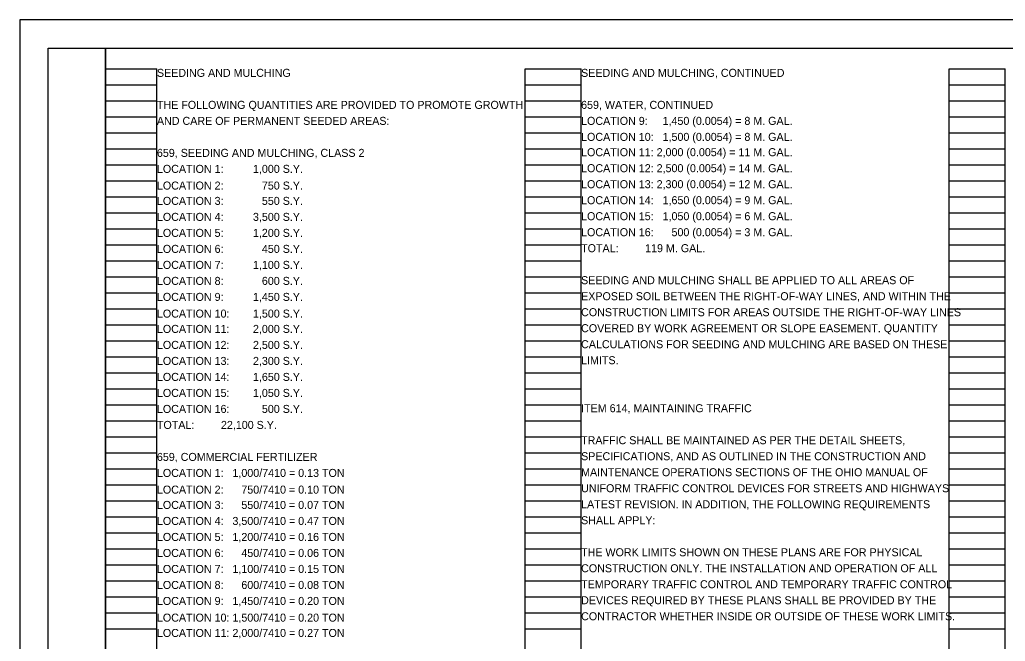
# Model space of a CAD drawing. Extents: x 0 to 34, y 0 to 22.
# Drawn here: x 0 to 17.24, y 11.12 to 22 of the extents above; entities that cross this region are included whole.
import ezdxf

# ---------------------------------------------------------------- set-up
doc = ezdxf.new("R2010")
doc.units = 0
for name, color, linetype in [('SH_Border', 7, 'Continuous'), ('SH_Cut_Line', 7, 'Continuous'), ('SH_Data', 7, 'Continuous'), ('SH_Text', 7, 'Continuous')]:
    doc.layers.add(name, color=color, linetype=linetype)

msp = doc.modelspace()

# ---------------------------------------------------------------- linework, layer by layer
at = {"layer": 'SH_Border'}
for points in [[(0.5, 21.5), (1.5, 21.5), (1.5, 0.5), (0.5, 0.5)], [(1.5, 21.5), (33.5, 21.5), (33.5, 0.5), (1.5, 0.5)]]:
    msp.add_lwpolyline(points, close=True, dxfattribs=at)
at = {"layer": 'SH_Cut_Line'}
msp.add_lwpolyline([(0, 0), (34, 0), (34, 22), (0, 22)], close=True, dxfattribs=at)
at = {"layer": 'SH_Data'}
for p, q in [((1.5, 0.98), (1.5, 21.14)), ((1.5, 21.14), (2.4, 21.14)), ((2.4, 0.98), (2.4, 21.14)), ((8.84, 0.98), (8.84, 21.14)), ((8.84, 21.14), (9.82, 21.14)), ((9.82, 0.98), (9.82, 21.14)), ((16.26, 0.98), (16.26, 21.14)), ((16.26, 21.14), (17.24, 21.14)), ((17.24, 0.98), (17.24, 21.14)), ((1.5, 20.86), (2.4, 20.86)), ((8.84, 20.86), (9.82, 20.86)), ((16.26, 20.86), (17.24, 20.86)), ((1.5, 20.58), (2.4, 20.58)), ((8.84, 20.58), (9.82, 20.58)), ((16.26, 20.58), (17.24, 20.58)), ((1.5, 20.3), (2.4, 20.3)), ((8.84, 20.3), (9.82, 20.3)), ((16.26, 20.3), (17.24, 20.3)), ((1.5, 20.02), (2.4, 20.02)), ((8.84, 20.02), (9.82, 20.02)), ((16.26, 20.02), (17.24, 20.02)), ((1.5, 19.74), (2.4, 19.74)), ((8.84, 19.74), (9.82, 19.74)), ((16.26, 19.74), (17.24, 19.74)), ((1.5, 19.46), (2.4, 19.46)), ((8.84, 19.46), (9.82, 19.46)), ((16.26, 19.46), (17.24, 19.46)), ((1.5, 19.18), (2.4, 19.18)), ((8.84, 19.18), (9.82, 19.18)), ((16.26, 19.18), (17.24, 19.18)), ((1.5, 18.9), (2.4, 18.9)), ((8.84, 18.9), (9.82, 18.9)), ((16.26, 18.9), (17.24, 18.9)), ((1.5, 18.62), (2.4, 18.62)), ((8.84, 18.62), (9.82, 18.62)), ((16.26, 18.62), (17.24, 18.62)), ((1.5, 18.34), (2.4, 18.34)), ((8.84, 18.34), (9.82, 18.34)), ((16.26, 18.34), (17.24, 18.34)), ((1.5, 18.06), (2.4, 18.06)), ((8.84, 18.06), (9.82, 18.06)), ((16.26, 18.06), (17.24, 18.06)), ((1.5, 17.78), (2.4, 17.78)), ((8.84, 17.78), (9.82, 17.78)), ((16.26, 17.78), (17.24, 17.78)), ((1.5, 17.5), (2.4, 17.5)), ((8.84, 17.5), (9.82, 17.5)), ((16.26, 17.5), (17.24, 17.5)), ((1.5, 17.22), (2.4, 17.22)), ((8.84, 17.22), (9.82, 17.22)), ((16.26, 17.22), (17.24, 17.22)), ((1.5, 16.94), (2.4, 16.94)), ((8.84, 16.94), (9.82, 16.94)), ((16.26, 16.94), (17.24, 16.94)), ((1.5, 16.66), (2.4, 16.66)), ((8.84, 16.66), (9.82, 16.66)), ((16.26, 16.66), (17.24, 16.66)), ((1.5, 16.38), (2.4, 16.38)), ((8.84, 16.38), (9.82, 16.38)), ((16.26, 16.38), (17.24, 16.38)), ((1.5, 16.1), (2.4, 16.1)), ((8.84, 16.1), (9.82, 16.1)), ((16.26, 16.1), (17.24, 16.1)), ((1.5, 15.82), (2.4, 15.82)), ((8.84, 15.82), (9.82, 15.82)), ((16.26, 15.82), (17.24, 15.82)), ((1.5, 15.54), (2.4, 15.54)), ((8.84, 15.54), (9.82, 15.54)), ((16.26, 15.54), (17.24, 15.54)), ((1.5, 15.26), (2.4, 15.26)), ((8.84, 15.26), (9.82, 15.26)), ((16.26, 15.26), (17.24, 15.26)), ((1.5, 14.98), (2.4, 14.98)), ((8.84, 14.98), (9.82, 14.98)), ((16.26, 14.98), (17.24, 14.98)), ((1.5, 14.7), (2.4, 14.7)), ((8.84, 14.7), (9.82, 14.7)), ((16.26, 14.7), (17.24, 14.7)), ((1.5, 14.42), (2.4, 14.42)), ((8.84, 14.42), (9.82, 14.42)), ((16.26, 14.42), (17.24, 14.42)), ((1.5, 14.14), (2.4, 14.14)), ((8.84, 14.14), (9.82, 14.14)), ((16.26, 14.14), (17.24, 14.14)), ((1.5, 13.86), (2.4, 13.86)), ((8.84, 13.86), (9.82, 13.86)), ((16.26, 13.86), (17.24, 13.86)), ((1.5, 13.58), (2.4, 13.58)), ((8.84, 13.58), (9.82, 13.58)), ((16.26, 13.58), (17.24, 13.58)), ((1.5, 13.3), (2.4, 13.3)), ((8.84, 13.3), (9.82, 13.3)), ((16.26, 13.3), (17.24, 13.3)), ((1.5, 13.02), (2.4, 13.02)), ((8.84, 13.02), (9.82, 13.02)), ((16.26, 13.02), (17.24, 13.02)), ((1.5, 12.74), (2.4, 12.74)), ((8.84, 12.74), (9.82, 12.74)), ((16.26, 12.74), (17.24, 12.74)), ((1.5, 12.46), (2.4, 12.46)), ((8.84, 12.46), (9.82, 12.46)), ((16.26, 12.46), (17.24, 12.46)), ((1.5, 12.18), (2.4, 12.18)), ((8.84, 12.18), (9.82, 12.18)), ((16.26, 12.18), (17.24, 12.18)), ((1.5, 11.9), (2.4, 11.9)), ((8.84, 11.9), (9.82, 11.9)), ((16.26, 11.9), (17.24, 11.9)), ((1.5, 11.62), (2.4, 11.62)), ((8.84, 11.62), (9.82, 11.62)), ((16.26, 11.62), (17.24, 11.62)), ((1.5, 11.34), (2.4, 11.34)), ((8.84, 11.34), (9.82, 11.34)), ((16.26, 11.34), (17.24, 11.34))]:
    msp.add_line(p, q, dxfattribs=at)

# ---------------------------------------------------------------- texts
at = {"layer": 'SH_Text'}
for s, p in [('SEEDING AND MULCHING', (2.4, 21)), ('SEEDING AND MULCHING, CONTINUED', (9.82, 21)), ('THE FOLLOWING QUANTITIES ARE PROVIDED TO PROMOTE GROWTH', (2.4, 20.44)), ('659, WATER, CONTINUED', (9.82, 20.44)), ('AND CARE OF PERMANENT SEEDED AREAS:', (2.4, 20.16)), ('LOCATION 9:     1,450 (0.0054) = 8 M. GAL.', (9.82, 20.16)), ('LOCATION 10:   1,500 (0.0054) = 8 M. GAL.', (9.82, 19.88)), ('659, SEEDING AND MULCHING, CLASS 2', (2.4, 19.6)), ('LOCATION 11: 2,000 (0.0054) = 11 M. GAL.', (9.82, 19.612)), ('LOCATION 1:', (2.4, 19.32)), ('1,000 S.Y.', (4.08, 19.32)), ('LOCATION 12: 2,500 (0.0054) = 14 M. GAL.', (9.82, 19.332)), ('LOCATION 2:', (2.4, 19.028)), ('   750 S.Y.', (4.08, 19.028)), ('LOCATION 13: 2,300 (0.0054) = 12 M. GAL.', (9.82, 19.052)), ('LOCATION 3:', (2.4, 18.76)), ('   550 S.Y.', (4.08, 18.76)), ('LOCATION 14:   1,650 (0.0054) = 9 M. GAL.', (9.82, 18.772)), ('LOCATION 4:', (2.4, 18.48)), ('3,500 S.Y.', (4.08, 18.48)), ('LOCATION 15:   1,050 (0.0054) = 6 M. GAL.', (9.82, 18.492)), ('LOCATION 5:', (2.4, 18.2)), ('1,200 S.Y.', (4.08, 18.2)), ('LOCATION 16:      500 (0.0054) = 3 M. GAL.', (9.82, 18.212)), ('LOCATION 6:', (2.4, 17.92)), ('   450 S.Y.', (4.08, 17.92)), ('TOTAL:', (9.82, 17.932)), ('119 M. GAL.', (10.94, 17.932)), ('LOCATION 7:', (2.4, 17.64)), ('1,100 S.Y.', (4.08, 17.64)), ('LOCATION 8:', (2.4, 17.36)), ('   600 S.Y.', (4.08, 17.36)), ('SEEDING AND MULCHING SHALL BE APPLIED TO ALL AREAS OF', (9.82, 17.372)), ('LOCATION 9:', (2.4, 17.08)), ('1,450 S.Y.', (4.08, 17.08)), ('EXPOSED SOIL BETWEEN THE RIGHT-OF-WAY LINES, AND WITHIN THE', (9.82, 17.092)), ('LOCATION 10:', (2.4, 16.788)), ('1,500 S.Y.', (4.08, 16.788)), ('CONSTRUCTION LIMITS FOR AREAS OUTSIDE THE RIGHT-OF-WAY LINES', (9.82, 16.812)), ('LOCATION 11:', (2.4, 16.52)), ('2,000 S.Y.', (4.08, 16.52)), ('COVERED BY WORK AGREEMENT OR SLOPE EASEMENT. QUANTITY', (9.82, 16.532)), ('LOCATION 12:', (2.4, 16.24)), ('2,500 S.Y.', (4.08, 16.24)), ('CALCULATIONS FOR SEEDING AND MULCHING ARE BASED ON THESE', (9.82, 16.252)), ('LOCATION 13:', (2.4, 15.96)), ('2,300 S.Y.', (4.08, 15.96)), ('LIMITS.', (9.82, 15.972)), ('LOCATION 14:', (2.4, 15.68)), ('1,650 S.Y.', (4.08, 15.68)), ('LOCATION 15:', (2.4, 15.4)), ('1,050 S.Y.', (4.08, 15.4)), ('LOCATION 16:', (2.4, 15.12)), ('   500 S.Y.', (4.08, 15.12)), ('ITEM 614, MAINTAINING TRAFFIC', (9.82, 15.132)), ('TOTAL:', (2.4, 14.84)), ('22,100 S.Y.', (3.52, 14.84)), ('TRAFFIC SHALL BE MAINTAINED AS PER THE DETAIL SHEETS,', (9.82, 14.572)), ('659, COMMERCIAL FERTILIZER', (2.4, 14.28)), ('SPECIFICATIONS, AND AS OUTLINED IN THE CONSTRUCTION AND', (9.82, 14.292)), ('LOCATION 1:   1,000/7410 = 0.13 TON', (2.4, 14)), ('MAINTENANCE OPERATIONS SECTIONS OF THE OHIO MANUAL OF', (9.82, 14.012)), ('LOCATION 2:      750/7410 = 0.10 TON', (2.4, 13.708)), ('UNIFORM TRAFFIC CONTROL DEVICES FOR STREETS AND HIGHWAYS', (9.82, 13.732)), ('LOCATION 3:      550/7410 = 0.07 TON', (2.4, 13.44)), ('LATEST REVISION. IN ADDITION, THE FOLLOWING REQUIREMENTS', (9.82, 13.452)), ('LOCATION 4:   3,500/7410 = 0.47 TON', (2.4, 13.16)), ('SHALL APPLY:', (9.82, 13.172)), ('LOCATION 5:   1,200/7410 = 0.16 TON', (2.4, 12.88)), ('LOCATION 6:      450/7410 = 0.06 TON', (2.4, 12.6)), ('THE WORK LIMITS SHOWN ON THESE PLANS ARE FOR PHYSICAL', (9.82, 12.612)), ('LOCATION 7:   1,100/7410 = 0.15 TON', (2.4, 12.32)), ('CONSTRUCTION ONLY. THE INSTALLATION AND OPERATION OF ALL', (9.82, 12.332)), ('LOCATION 8:      600/7410 = 0.08 TON', (2.4, 12.04)), ('TEMPORARY TRAFFIC CONTROL AND TEMPORARY TRAFFIC CONTROL', (9.82, 12.052)), ('LOCATION 9:   1,450/7410 = 0.20 TON', (2.4, 11.76)), ('DEVICES REQUIRED BY THESE PLANS SHALL BE PROVIDED BY THE', (9.82, 11.772)), ('LOCATION 10: 1,500/7410 = 0.20 TON', (2.4, 11.468)), ('CONTRACTOR WHETHER INSIDE OR OUTSIDE OF THESE WORK LIMITS.', (9.82, 11.492)), ('LOCATION 11: 2,000/7410 = 0.27 TON', (2.4, 11.2))]:
    msp.add_text(s, height=0.14, dxfattribs=at).set_placement(p)

doc.saveas('drawing.dxf')
